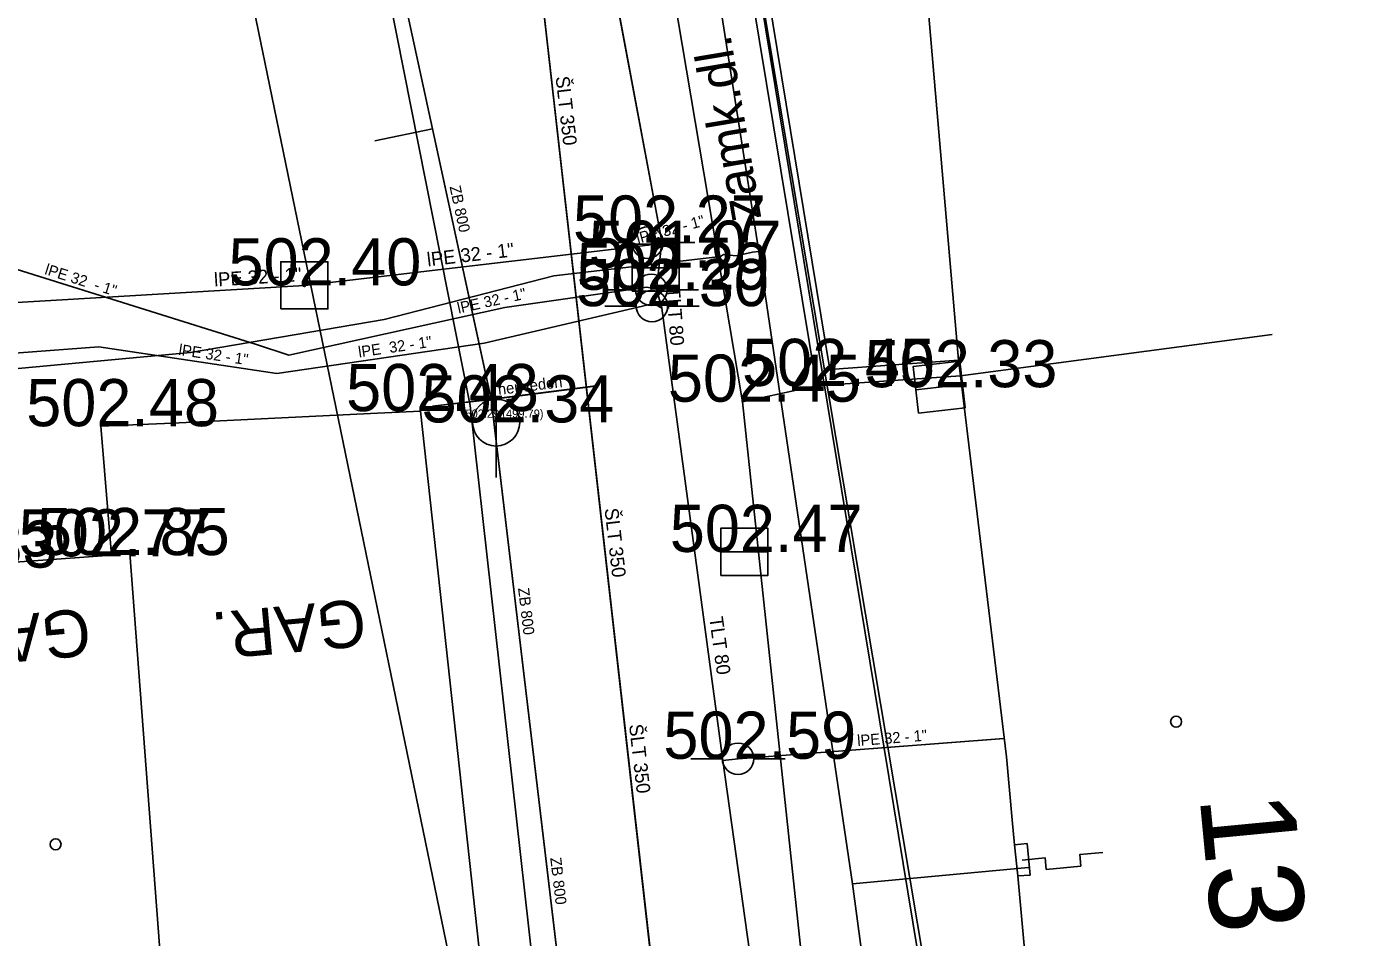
# Model space of a CAD drawing. Extents: x -669642 to -669119, y -1131006 to -1130466.
# Drawn here: x -669402.08 to -669380.72, y -1130782.23 to -1130767.75 of the extents above; entities that cross this region are included whole.
import ezdxf

# ---------------------------------------------------------------- set-up
doc = ezdxf.new("R2010")
doc.units = 0
for name, color, linetype in [('G_Bod_tecka', 7, 'Continuous'), ('G_Bod_vyska', 7, 'Continuous'), ('G_Budovy-znacky', 7, 'Continuous'), ('G_Budovy_Objekty', 7, 'Continuous'), ('G_Budovy_vstupy', 7, 'Continuous'), ('G_Cesty_Schody', 7, 'Continuous'), ('G_Cisla_orientacni', 7, 'Continuous'), ('G_Plochy_zpevnene', 7, 'Continuous'), ('G_Ploty', 7, 'Continuous'), ('G_Ploty_vstupy', 7, 'Continuous'), ('G_Popisy_objektu', 7, 'Continuous'), ('G_Popisy_povrchu', 7, 'Continuous'), ('G_Site-kanalizace', 7, 'Continuous'), ('G_Site-Rozvadece', 7, 'Continuous'), ('G_Site-Sachty_N', 7, 'Continuous'), ('G_Site-vodovod', 7, 'Continuous'), ('G_Z_ELsilove_nadz_kotovane', 7, 'Continuous'), ('G_Z_ELsilove_podz_kotovane', 7, 'Continuous'), ('G_Z_KANAL_podz_kotovane', 7, 'Continuous'), ('G_Z_PLYNY_podz_geodeticky', 7, 'Continuous'), ('G_Z_SPOJE_nadz_kotovane', 7, 'Continuous'), ('G_Z_VODA_podz_kotovane', 7, 'Continuous'), ('Vrstva 12', 7, 'Continuous'), ('Vrstva 13', 7, 'Continuous'), ('Vrstva 2', 7, 'Continuous'), ('Vrstva 26', 7, 'Continuous'), ('Vrstva 3', 7, 'Continuous'), ('Vrstva 4', 7, 'Continuous'), ('Vrstva 5', 7, 'Continuous'), ('Vrstva 6', 7, 'Continuous'), ('Vrstva 8', 7, 'Continuous')]:
    doc.layers.add(name, color=color, linetype=linetype)

msp = doc.modelspace()

# ---------------------------------------------------------------- linework, layer by layer
at = {"layer": 'G_Bod_tecka'}
for p, q in [((-669392.2, -1130771.18), (-669392.2, -1130771.18)), ((-669392.07, -1130771.58), (-669392.07, -1130771.58)), ((-669397.66, -1130771.86), (-669397.66, -1130771.86)), ((-669392.14, -1130771.93), (-669392.14, -1130771.93)), ((-669392.13, -1130772.19), (-669392.13, -1130772.19)), ((-669389.51, -1130773.46), (-669389.51, -1130773.46)), ((-669387.56, -1130773.48), (-669387.56, -1130773.48)), ((-669390.69, -1130773.71), (-669390.69, -1130773.71)), ((-669395.81, -1130773.86), (-669395.81, -1130773.86)), ((-669400.9, -1130774.1), (-669400.9, -1130774.1)), ((-669394.61, -1130774.04), (-669394.61, -1130774.04)), ((-669400.73, -1130776.15), (-669400.73, -1130776.15)), ((-669390.66, -1130776.1), (-669390.66, -1130776.1)), ((-669401.02, -1130776.17), (-669401.02, -1130776.17)), ((-669390.76, -1130779.39), (-669390.76, -1130779.39))]:
    msp.add_line(p, q, dxfattribs=at)
at = {"layer": 'G_Budovy-znacky'}
for centre in [(-669383.789, -1130778.8), (-669401.619, -1130780.751)]:
    msp.add_circle(centre, 0.0875, dxfattribs=at)
at = {"layer": 'G_Budovy_Objekty'}
for p, q in [((-669387.96, -1130764.86), (-669387.25, -1130773.05)), ((-669382.26, -1130772.64), (-669387.22, -1130773.3)), ((-669387.25, -1130773.05), (-669387.22, -1130773.3)), ((-669387.22, -1130773.3), (-669386.49, -1130779.36)), ((-669396.61, -1130773.9), (-669395.81, -1130773.86)), ((-669395.81, -1130773.86), (-669394.4, -1130786.8)), ((-669400.9, -1130774.1), (-669399.76, -1130774.05)), ((-669400.73, -1130776.15), (-669400.9, -1130774.1)), ((-669400.73, -1130776.15), (-669401.02, -1130776.17)), ((-669400.44, -1130776.12), (-669400.73, -1130776.15)), ((-669399.6, -1130787.15), (-669400.44, -1130776.12)), ((-669386.4, -1130780.36), (-669386.36, -1130780.76)), ((-669386.36, -1130780.76), (-669386.31, -1130781.25)), ((-669386.31, -1130781.25), (-669385.84, -1130786.26))]:
    msp.add_line(p, q, dxfattribs=at)
at = {"layer": 'G_Budovy_vstupy'}
for p, q in [((-669401.02, -1130776.17), (-669403.47, -1130776.35)), ((-669386.49, -1130779.36), (-669386.4, -1130780.36))]:
    msp.add_line(p, q, dxfattribs=at)
at = {"layer": 'G_Cesty_Schody'}
msp.add_line((-669389.51, -1130773.46), (-669390.69, -1130773.71), dxfattribs=at)
at = {"layer": 'G_Plochy_zpevnene'}
msp.add_line((-669395.02, -1130773.77), (-669390.94, -1130810.19), dxfattribs=at)
for points in [[(-669400.19, -1130747.71), (-669395.02, -1130773.77)], [(-669393.29, -1130758.32), (-669390.69, -1130773.71), (-669389.32, -1130786.56)]]:
    msp.add_lwpolyline(points, dxfattribs=at)
at = {"layer": 'G_Ploty'}
for p, q in [((-669389.51, -1130773.46), (-669390.82, -1130765.53)), ((-669389.3, -1130773.2), (-669390.57, -1130765.49)), ((-669387.25, -1130773.05), (-669389.3, -1130773.2)), ((-669387.22, -1130773.3), (-669389.51, -1130773.46))]:
    msp.add_line(p, q, dxfattribs=at)
at = {"layer": 'G_Ploty_vstupy'}
msp.add_line((-669396.61, -1130773.9), (-669399.76, -1130774.05), dxfattribs=at)
at = {"layer": 'G_Site-kanalizace'}
for points in [[(-669392.445, -1130771.954), (-669391.695, -1130771.954), (-669391.695, -1130771.204), (-669392.445, -1130771.204)], [(-669387.889, -1130773.895), (-669387.144, -1130773.807), (-669387.232, -1130773.063), (-669387.976, -1130773.151)], [(-669391.035, -1130776.474), (-669390.285, -1130776.474), (-669390.285, -1130775.724), (-669391.035, -1130775.724)]]:
    msp.add_lwpolyline(points, close=True, dxfattribs=at)
for points in [[(-669392.445, -1130771.58), (-669391.695, -1130771.58)], [(-669387.932, -1130773.524), (-669387.188, -1130773.436)], [(-669394.61, -1130773.665), (-669394.61, -1130774.915)], [(-669391.035, -1130776.1), (-669390.285, -1130776.1)]]:
    msp.add_lwpolyline(points, dxfattribs=at)
msp.add_circle((-669394.609, -1130774.04), 0.375, dxfattribs=at)
at = {"layer": 'G_Site-Rozvadece'}
for p, q in [((-669386.36, -1130780.76), (-669386.16, -1130780.74)), ((-669386.16, -1130780.74), (-669386.11, -1130781.24)), ((-669386.11, -1130781.24), (-669386.31, -1130781.25))]:
    msp.add_line(p, q, dxfattribs=at)
msp.add_lwpolyline([(-669386.24, -1130781.001), (-669385.873, -1130780.967), (-669385.856, -1130781.149), (-669385.306, -1130781.097), (-669385.323, -1130780.915), (-669384.956, -1130780.879)], dxfattribs=at)
at = {"layer": 'G_Site-Sachty_N'}
msp.add_lwpolyline([(-669398.035, -1130772.235), (-669397.285, -1130772.235), (-669397.285, -1130771.485), (-669398.035, -1130771.485)], close=True, dxfattribs=at)
msp.add_circle((-669397.66, -1130771.86), 0.02, dxfattribs=at)
at = {"layer": 'G_Site-vodovod'}
for points in [[(-669392.45, -1130771.18), (-669392.95, -1130771.18)], [(-669391.95, -1130771.18), (-669391.45, -1130771.18)], [(-669392.39, -1130771.93), (-669392.89, -1130771.93)], [(-669391.89, -1130771.93), (-669391.39, -1130771.93)], [(-669392.38, -1130772.19), (-669392.88, -1130772.19)], [(-669391.88, -1130772.19), (-669391.38, -1130772.19)], [(-669391.01, -1130779.39), (-669391.51, -1130779.39)], [(-669390.51, -1130779.39), (-669390.01, -1130779.39)]]:
    msp.add_lwpolyline(points, dxfattribs=at)
for centre in [(-669392.2, -1130771.18), (-669392.14, -1130771.93), (-669392.13, -1130772.19), (-669390.76, -1130779.39)]:
    msp.add_circle(centre, 0.25, dxfattribs=at)
at = {"layer": 'G_Z_ELsilove_nadz_kotovane'}
msp.add_lwpolyline([(-669396.504, -1130732), (-669391.98, -1130757.716), (-669387.149, -1130787.013)], dxfattribs=at)
at = {"layer": 'G_Z_ELsilove_podz_kotovane'}
msp.add_lwpolyline([(-669391.83, -1130758.66), (-669387.04, -1130787.16), (-669380.84, -1130853.82), (-669376.27, -1130911.91), (-669375.45, -1130932.67), (-669367.41, -1130949.86), (-669354.28, -1130962.65), (-669322.79, -1130989.32), (-669305.7, -1131000.09), (-669304.07, -1131000.6)], dxfattribs=at)
at = {"layer": 'G_Z_KANAL_podz_kotovane'}
for p, q in [((-669395.62, -1130769.37), (-669396.54, -1130769.56)), ((-669394.69, -1130773.67), (-669393.03, -1130773.46)), ((-669394.69, -1130773.67), (-669395.62, -1130773.78))]:
    msp.add_line(p, q, dxfattribs=at)
for points in [[(-669394.69, -1130773.67), (-669395.62, -1130769.37), (-669397.4, -1130761.18), (-669397.96, -1130758.61), (-669398.24, -1130756.09), (-669399.58, -1130744.19), (-669400.54, -1130735.66), (-669400.97, -1130731.84), (-669401.06, -1130731.05), (-669402.01, -1130726.02), (-669401.65, -1130724.4), (-669401.82, -1130723.24), (-669402.71, -1130717.15), (-669403.44, -1130712.15), (-669404.01, -1130708.24), (-669405.38, -1130698.86), (-669405.54, -1130697.79)], [(-669386.05, -1130847.79), (-669389.19, -1130819.89), (-669390.06, -1130812.55), (-669394.69, -1130773.67)]]:
    msp.add_lwpolyline(points, dxfattribs=at)
at = {"layer": 'G_Z_PLYNY_podz_geodeticky'}
for points in [[(-669400.98, -1130689.56), (-669400.99, -1130709.56), (-669398.76, -1130723.26), (-669397.99, -1130727.16), (-669397.8, -1130727.9), (-669397.32, -1130731.57), (-669394.97, -1130744.51), (-669391.88, -1130762.42), (-669391.21, -1130766.34), (-669390.43, -1130771.32)], [(-669390.79, -1130771.39), (-669390.99, -1130771.37), (-669391.04, -1130771.4), (-669393.69, -1130771.71), (-669396.39, -1130772.4), (-669399.47, -1130772.93)], [(-669390.53, -1130771.33), (-669390.79, -1130771.39)], [(-669390.43, -1130771.32), (-669390.53, -1130771.33)], [(-669390.43, -1130771.32), (-669388.94, -1130781.38), (-669387.27, -1130793.84), (-669384.52, -1130818.24), (-669383.72, -1130826.65), (-669382.93, -1130835.15), (-669382.21, -1130842.83), (-669381.73, -1130851.41), (-669380.44, -1130861.77), (-669378.34, -1130882.46)], [(-669399.47, -1130772.93), (-669402.96, -1130773.25), (-669404.67, -1130773.78), (-669405.92, -1130774.31), (-669406.29, -1130774.46), (-669406.39, -1130774.5)], [(-669388.94, -1130781.38), (-669386.14, -1130781.12)]]:
    msp.add_lwpolyline(points, dxfattribs=at)
at = {"layer": 'G_Z_SPOJE_nadz_kotovane'}
msp.add_lwpolyline([(-669406.55, -1130722.06), (-669400.29, -1130758.6), (-669393.51, -1130791.5)], dxfattribs=at)
at = {"layer": 'G_Z_VODA_podz_kotovane'}
msp.add_line((-669391.97, -1130771.16), (-669392.19, -1130771.22), dxfattribs=at)
for points in [[(-669387.02, -1130812.53), (-669389.23, -1130792.08), (-669391, -1130779.42), (-669391.97, -1130772.22), (-669392.06, -1130771.92), (-669391.97, -1130771.16), (-669393.13, -1130764.98), (-669393.69, -1130761.37), (-669394.75, -1130753.04), (-669396.24, -1130745.91), (-669399.34, -1130731.13), (-669400.46, -1130726.23), (-669400.61, -1130725.04), (-669400.78, -1130724.52), (-669402.59, -1130713.28), (-669402.7, -1130712.61), (-669402.95, -1130701.47), (-669402.25, -1130693.89), (-669402.71, -1130680.24), (-669402.15, -1130669.87), (-669400.75, -1130656.95), (-669398.85, -1130641.75)], [(-669403.09, -1130650.73), (-669405.21, -1130670.54), (-669406.48, -1130689.47), (-669407.14, -1130697.84), (-669406.32, -1130715.38), (-669403.7, -1130729.64), (-669400.71, -1130745.88), (-669399.15, -1130753.32), (-669398.52, -1130755.36), (-669396.1, -1130756.91), (-669395.09, -1130760.49), (-669394.09, -1130765.4), (-669391.66, -1130786.81), (-669388.98, -1130811.25)], [(-669440.56, -1130777.1), (-669435.63, -1130776.37), (-669431.46, -1130775.69), (-669421.48, -1130774.06), (-669410.97, -1130772.69), (-669404.93, -1130772.29), (-669397.66, -1130771.86), (-669392.19, -1130771.22)], [(-669392.06, -1130771.92), (-669392.21, -1130771.89), (-669394.47, -1130772.21), (-669397.91, -1130772.97), (-669398.42, -1130772.8), (-669404.01, -1130771.05), (-669406.07, -1130771.07), (-669415.35, -1130772.2)], [(-669391.97, -1130772.22), (-669392.1, -1130772.15), (-669394.8, -1130772.78), (-669398.1, -1130773.26), (-669400.93, -1130772.84), (-669403.47, -1130773.03), (-669405.68, -1130774.85), (-669409.29, -1130778.28), (-669410.11, -1130778.71)], [(-669391, -1130779.42), (-669390.76, -1130779.39), (-669386.53, -1130779.07)]]:
    msp.add_lwpolyline(points, dxfattribs=at)
at = {"layer": 'Vrstva 12'}
for points in [[(-669394.689, -1130773.674), (-669395.624, -1130769.369), (-669397.401, -1130761.182), (-669397.96, -1130758.61), (-669398.244, -1130756.087), (-669399.582, -1130744.192), (-669400.541, -1130735.664), (-669400.971, -1130731.838), (-669401.06, -1130731.05), (-669402.007, -1130726.018), (-669401.65, -1130724.4), (-669401.819, -1130723.242), (-669402.711, -1130717.147), (-669403.441, -1130712.15), (-669404.013, -1130708.242), (-669405.385, -1130698.862), (-669405.541, -1130697.793)], [(-669386.05, -1130847.79), (-669389.185, -1130819.892), (-669390.059, -1130812.552), (-669394.689, -1130773.674)]]:
    msp.add_lwpolyline(points, dxfattribs=at)
at = {"layer": 'Vrstva 13'}
for p, q in [((-669395.624, -1130769.369), (-669396.541, -1130769.563)), ((-669394.689, -1130773.674), (-669393.027, -1130773.464)), ((-669394.689, -1130773.674), (-669395.618, -1130773.781))]:
    msp.add_line(p, q, dxfattribs=at)
at = {"layer": 'Vrstva 26'}
msp.add_line((-669391.97, -1130771.16), (-669392.19, -1130771.22), dxfattribs=at)
for points in [[(-669387.019, -1130812.528), (-669389.231, -1130792.082), (-669391.001, -1130779.42), (-669391.97, -1130772.22), (-669392.06, -1130771.92), (-669391.97, -1130771.16), (-669393.133, -1130764.977), (-669393.689, -1130761.37), (-669394.75, -1130753.038), (-669396.244, -1130745.914), (-669399.343, -1130731.135), (-669400.461, -1130726.23), (-669400.612, -1130725.037), (-669400.78, -1130724.52), (-669402.594, -1130713.284), (-669402.695, -1130712.614), (-669402.948, -1130701.466), (-669402.247, -1130693.89), (-669402.705, -1130680.236), (-669402.147, -1130669.872), (-669400.746, -1130656.946), (-669398.853, -1130641.75)], [(-669403.087, -1130650.733), (-669405.214, -1130670.54), (-669406.476, -1130689.467), (-669407.14, -1130697.842), (-669406.32, -1130715.384), (-669403.695, -1130729.64), (-669400.705, -1130745.879), (-669399.153, -1130753.32), (-669398.519, -1130755.364), (-669396.099, -1130756.914), (-669395.09, -1130760.491), (-669394.091, -1130765.401), (-669391.664, -1130786.81), (-669388.978, -1130811.253)], [(-669440.56, -1130777.1), (-669435.63, -1130776.37), (-669431.46, -1130775.69), (-669421.48, -1130774.06), (-669410.97, -1130772.69), (-669404.93, -1130772.29), (-669397.66, -1130771.86), (-669392.19, -1130771.22)], [(-669392.06, -1130771.92), (-669392.21, -1130771.89), (-669394.47, -1130772.21), (-669397.91, -1130772.97), (-669398.42, -1130772.8), (-669404.01, -1130771.05), (-669406.07, -1130771.07), (-669415.349, -1130772.202)], [(-669391.97, -1130772.22), (-669392.1, -1130772.15), (-669394.8, -1130772.78), (-669398.1, -1130773.26), (-669400.93, -1130772.84), (-669403.47, -1130773.03), (-669405.68, -1130774.85), (-669409.29, -1130778.28), (-669410.11, -1130778.71)], [(-669391.001, -1130779.42), (-669390.76, -1130779.39), (-669386.528, -1130779.066)]]:
    msp.add_lwpolyline(points, dxfattribs=at)
at = {"layer": 'Vrstva 5'}
for p, q in [((-669391.83, -1130758.66), (-669387.04, -1130787.16)), ((-669387.04, -1130787.16), (-669391.83, -1130758.66))]:
    msp.add_line(p, q, dxfattribs=at)
at = {"layer": 'Vrstva 6'}
for p, q in [((-669392.19, -1130771.22), (-669392.19, -1130771.22)), ((-669392.21, -1130771.89), (-669392.21, -1130771.89)), ((-669392.1, -1130772.15), (-669392.1, -1130772.15)), ((-669390.76, -1130779.39), (-669390.76, -1130779.39))]:
    msp.add_line(p, q, dxfattribs=at)
at = {"layer": 'Vrstva 8'}
msp.add_line((-669394.689, -1130773.674), (-669394.689, -1130773.674), dxfattribs=at)

# ---------------------------------------------------------------- texts
at = {"layer": 'G_Bod_vyska'}
for s, p in [('502.27', (-669393.386, -1130771.18)), ('501.07', (-669393.136, -1130771.58)), ('502.40', (-669398.867, -1130771.86)), ('502.29', (-669393.328, -1130771.93)), ('502.30', (-669393.337, -1130772.19)), ('502.45', (-669390.696, -1130773.46)), ('502.33', (-669388.746, -1130773.48)), ('502.45', (-669391.876, -1130773.71)), ('502.43', (-669396.996, -1130773.86)), ('502.48', (-669402.086, -1130774.1)), ('502.34', (-669395.796, -1130774.04)), ('502.77', (-669402.206, -1130776.17)), ('502.85', (-669401.916, -1130776.15)), ('502.47', (-669391.846, -1130776.1)), ('502.83', (-669404.656, -1130776.35)), ('502.59', (-669391.948, -1130779.39))]:
    msp.add_text(s, height=0.75, dxfattribs=at).set_placement(p)
at = {"layer": 'G_Cisla_orientacni'}
msp.add_text('13', height=1.5, rotation=275.4559, dxfattribs=at).set_placement((-669383.418, -1130779.993))
at = {"layer": 'G_Popisy_objektu'}
for p in [(-669401.099, -1130776.994), (-669396.719, -1130776.844)]:
    msp.add_text('GAR.', height=0.75, rotation=185.2514, dxfattribs=at).set_placement(p)
at = {"layer": 'G_Popisy_povrchu'}
msp.add_text('zamk.dl.', height=0.6, rotation=99.5891, dxfattribs=at).set_placement((-669390.387, -1130770.796))
at = {"layer": 'Vrstva 2'}
msp.add_text('502.29 (499.79)', height=0.13163, dxfattribs=at).set_placement((-669395.098, -1130773.966))
at = {"layer": 'Vrstva 3'}
for s, rotation, p in [('ZB 800', 282.2605, (-669395.351, -1130770.291)), ('neuveden', 7.0161, (-669394.57, -1130773.603)), ('ZB 800', 276.7928, (-669394.261, -1130776.678)), ('ZB 800', 276.7573, (-669393.749, -1130780.969))]:
    msp.add_text(s, height=0.1755, rotation=rotation, dxfattribs=at).set_placement(p)
at = {"layer": 'Vrstva 4'}
for s, height, rotation, p in [('ŠLT 350', 0.2194, 276.5255, (-669393.664, -1130768.543)), ('lPE 32 - 1"', 0.17551, 15.2103, (-669392.352, -1130771.2)), ('lPE 32 - 1"', 0.21938, 6.637, (-669395.697, -1130771.559)), ('lPE 32  - 1"', 0.17551, 342.4608, (-669401.804, -1130771.678)), ('lPE 32 - 1"', 0.21938, 3.5616, (-669399.091, -1130771.879)), ('TLT 80', 0.2194, 274.3806, (-669391.904, -1130771.9)), ('lPE 32 - 1"', 0.17551, 12.4326, (-669395.207, -1130772.309)), ('lPE  32 - 1"', 0.17551, 8.28, (-669396.79, -1130773.007)), ('lPE 32 - 1"', 0.17551, 351.5543, (-669399.67, -1130772.965)), ('ŠLT 350', 0.2194, 276.497, (-669392.885, -1130775.414)), ('TLT 80', 0.2194, 277.8326, (-669391.22, -1130777.145)), ('ŠLT 350', 0.2194, 276.5239, (-669392.495, -1130778.85)), ('lPE 32 - 1"', 0.17551, 4.5225, (-669388.857, -1130779.189))]:
    msp.add_text(s, height=height, rotation=rotation, dxfattribs=at).set_placement(p)

doc.saveas('drawing.dxf')
